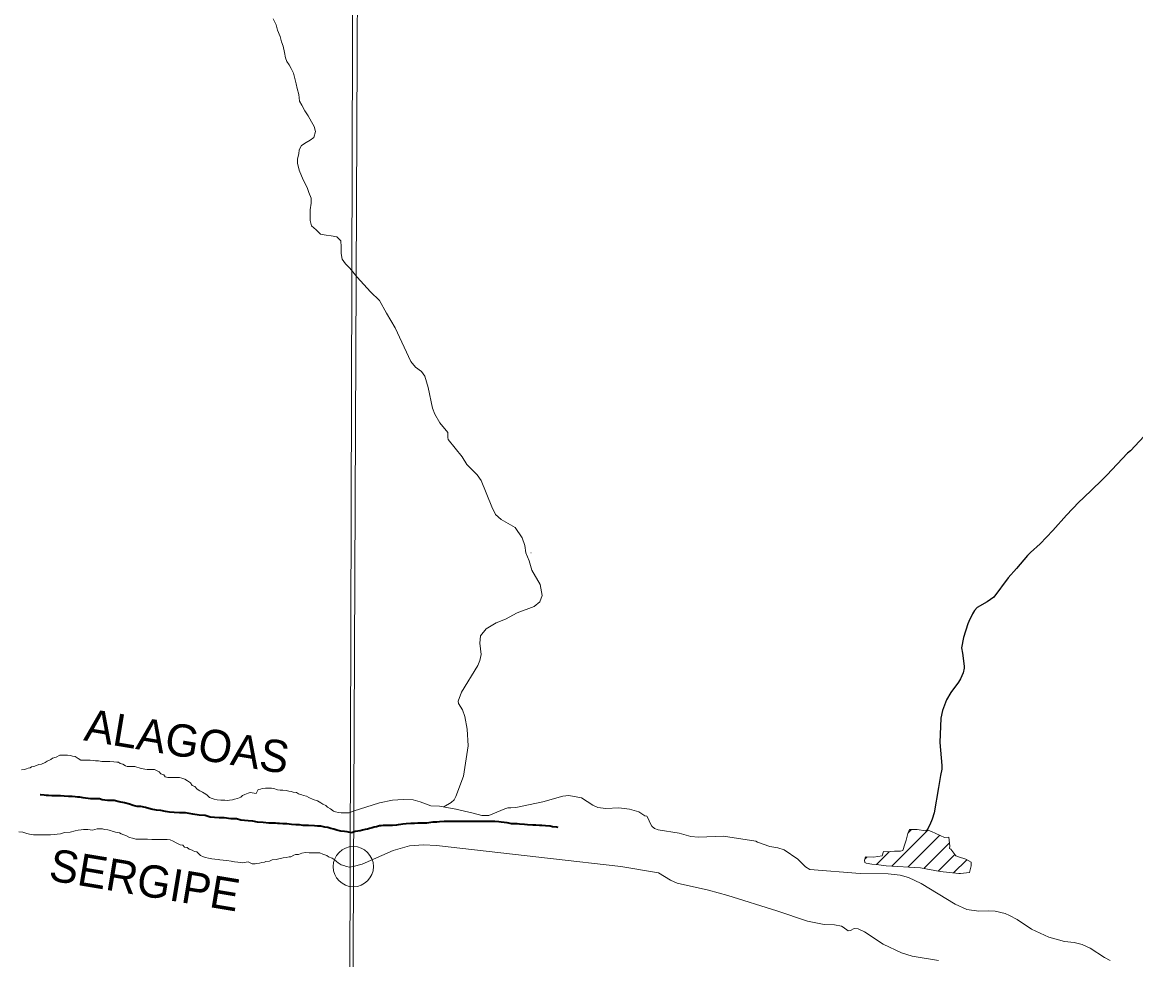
# Model space of a CAD drawing. Extents: x -1643653 to 4543381, y 1624270 to 13878484.
# Drawn here: x 595746 to 598511, y 8904160 to 8906488 of the extents above; entities that cross this region are included whole.
import ezdxf
from ezdxf.enums import TextEntityAlignment as Align

# ---------------------------------------------------------------- set-up
doc = ezdxf.new("R2010")
doc.units = 0
doc.header["$LTSCALE"] = 200
doc.header["$PDMODE"] = 32
doc.header["$PDSIZE"] = 100
doc.linetypes.add('LONG_DASH_SHORT_DASH', pattern=[9.9, 6, -1.2, 1.5, -1.2])
doc.layers.add('6', color=7, linetype='Continuous', lineweight=13)
doc.layers.add('60', color=7, linetype='Continuous', lineweight=13)

msp = doc.modelspace()

# ---------------------------------------------------------------- linework, layer by layer
at = {"layer": '6'}
for p, q in [((597009.3, 8905170.6), (597009.5, 8905170.5)), ((597905.6, 8904392.3), (597995.3, 8904482)), ((597946.4, 8904475.5), (597954.7, 8904483.9)), ((597945.7, 8904390), (598025, 8904469.3)), ((597867.6, 8904396.8), (597899.4, 8904428.5)), ((597984.9, 8904386.8), (598049.1, 8904451)), ((597838.3, 8904409.9), (597844.2, 8904415.7)), ((598021.1, 8904380.5), (598062.5, 8904421.9)), ((598059, 8904376), (598091.6, 8904408.6))]:
    msp.add_line(p, q, dxfattribs=at)
for points in [[(596655.5, 8924715.8), (596593.3, 8909930.3), (596531.7, 8896026.7)], [(596461.2, 8906005.4), (596461.2, 8906022.7), (596463.8, 8906039.2), (596463.4, 8906051.2), (596457.4, 8906065.3), (596453.5, 8906078.3), (596444.6, 8906095.4), (596439.1, 8906106.9), (596433.7, 8906120.9), (596429.8, 8906138.5), (596429.8, 8906149), (596432.9, 8906162), (596433.9, 8906171.5), (596439.5, 8906182), (596451, 8906189.9), (596461, 8906195.4), (596470.1, 8906202.3), (596474.2, 8906216.8), (596471.2, 8906229.4), (596464.2, 8906241.4), (596455.8, 8906256), (596447.9, 8906268), (596439.9, 8906282.6), (596434.5, 8906292.6), (596433, 8906308.7), (596429.1, 8906323.7), (596426.2, 8906335.2), (596422.7, 8906348.8), (596419.3, 8906361.8), (596413.8, 8906373.3), (596408.8, 8906382.4), (596403.4, 8906390.9), (596399.9, 8906400.4), (596397, 8906413.4), (596393.6, 8906429), (596389.6, 8906440), (596386.2, 8906452.6), (596379.7, 8906468.6), (596376.3, 8906481.6), (596368.8, 8906497.2)], [(596838.8, 8905408.9), (596804, 8905452.2), (596802.6, 8905456.8), (596803.3, 8905469.9), (596782.8, 8905493.9), (596770.6, 8905515.5), (596764.7, 8905530.2), (596754.3, 8905581.4), (596745.9, 8905609.6), (596737.4, 8905621.2), (596722.8, 8905631.7), (596710.6, 8905646), (596672.1, 8905729.1), (596650.2, 8905765.8), (596633.6, 8905797.4), (596611.2, 8905818.6), (596577.4, 8905855.5), (596559.7, 8905877.5), (596548.7, 8905888.6), (596540.2, 8905900.2), (596538.3, 8905914.2), (596537.9, 8905930.7), (596537.5, 8905945.2), (596527, 8905955.3), (596513.5, 8905957.9), (596500.5, 8905959.4), (596487, 8905962.5), (596476, 8905972.6), (596464.6, 8905983.1), (596461.1, 8905995.7), (596461.2, 8906005.4)], [(596792.7, 8904540.1), (596811.4, 8904551.1), (596818.4, 8904557.4), (596822.7, 8904565.5), (596841.5, 8904615.9), (596853.2, 8904691.8), (596850.7, 8904732.7), (596845.1, 8904764.5), (596839.3, 8904781), (596829.4, 8904796.5), (596828.9, 8904802.2), (596837.1, 8904824.7), (596877.1, 8904890.7), (596882.8, 8904903.4), (596885.5, 8904918), (596882.5, 8904946.3), (596884.2, 8904964.5), (596897.9, 8904982), (596922.6, 8904996.6), (596946.5, 8905006.2), (596975.3, 8905021.5), (597017.5, 8905037.8), (597031.8, 8905049.4), (597037, 8905065), (597032.3, 8905091.9), (597011.4, 8905127.4), (597004.9, 8905150.7), (596996.7, 8905170.4), (596994.1, 8905188.6), (596987.3, 8905208), (596969.8, 8905234), (596935.4, 8905253.2), (596921.5, 8905266.1), (596912.2, 8905285.1), (596886, 8905350.5), (596875.4, 8905364.7), (596850.4, 8905390), (596838.8, 8905408.9)], [(595744.1, 8904632.1), (595751.7, 8904633.1), (595756.2, 8904634.6), (595760.7, 8904636), (595765.2, 8904637), (595769.2, 8904639), (595774.7, 8904640.4), (595781.2, 8904642.4), (595786.8, 8904645.4), (595793.3, 8904646.3), (595802.8, 8904650.3), (595807.8, 8904653.7), (595816.9, 8904657.2), (595821.4, 8904660.7), (595830.4, 8904663.6), (595839, 8904668.1), (595845, 8904668), (595850, 8904668), (595858, 8904667.9), (595866, 8904667.4), (595870.5, 8904665.8), (595877.5, 8904664.8), (595884.9, 8904659.7), (595891.4, 8904656.2), (595899.4, 8904656.1), (595903.4, 8904656.1), (595910.9, 8904656.1), (595914.9, 8904656), (595922.9, 8904655), (595927.4, 8904654.4), (595934.9, 8904653.9), (595943.4, 8904652.3), (595951.4, 8904652.3), (595956.4, 8904652.3), (595963.4, 8904652.2), (595973.4, 8904651.6), (595980.4, 8904651.1), (595984.9, 8904650.6), (595989.4, 8904647.5), (595995.3, 8904646), (596002.3, 8904641.9), (596006.8, 8904639.9), (596012.8, 8904639.9), (596025.8, 8904639.8), (596041.3, 8904635.2), (596045.8, 8904634.6), (596050.3, 8904633.6), (596056.3, 8904633.1), (596063.8, 8904633), (596067.8, 8904633), (596074.3, 8904632.4), (596079.3, 8904630.4), (596086.2, 8904626.9), (596090.2, 8904622.3), (596097.2, 8904619.3), (596100.7, 8904614.2), (596107.2, 8904613.2), (596113.7, 8904613.2), (596120.7, 8904613.1), (596124.7, 8904613.1), (596128.7, 8904613.1), (596136.2, 8904613), (596142.2, 8904611), (596149.6, 8904608.4), (596156.1, 8904604.4), (596163.6, 8904599.3), (596168, 8904593.3), (596174.5, 8904590.2), (596180.5, 8904583.7), (596186.9, 8904580.1), (596193.4, 8904576.1), (596197.9, 8904574.1), (596204.4, 8904570), (596211.3, 8904563.4), (596217.3, 8904560.4), (596222.8, 8904558.9), (596229.8, 8904557.3), (596238.8, 8904556.3), (596245.3, 8904556.2), (596249.3, 8904556.2), (596255.8, 8904556.1), (596260.3, 8904556.6), (596268.3, 8904557.6), (596272.8, 8904559), (596280.8, 8904561), (596288.9, 8904564.4), (596292.9, 8904567.9), (596298.4, 8904570.9), (596307, 8904574.3), (596312, 8904575.3), (596327, 8904573.2), (596331.5, 8904582.7), (596337.5, 8904584.1)], [(596337.5, 8904584.1), (596341.6, 8904585.6), (596350.1, 8904586.6), (596357.6, 8904586.5), (596364.6, 8904586), (596371.1, 8904585.9), (596379.5, 8904581.9), (596386.5, 8904581.3), (596393.5, 8904581.3), (596401.5, 8904580.7), (596408, 8904579.2), (596414, 8904578.1), (596419, 8904576.6), (596427, 8904575.5), (596432, 8904572.5), (596440, 8904569.4), (596444.5, 8904567.9), (596452, 8904566.9), (596457.4, 8904563.3), (596468.4, 8904558.2), (596478.9, 8904554.7), (596487.3, 8904550.1), (596492.3, 8904546.6), (596500.3, 8904543), (596504.3, 8904539), (596511.7, 8904535.4), (596519.2, 8904529.4), (596523.7, 8904527.8), (596531.7, 8904525.8), (596538.2, 8904524.7), (596545.2, 8904524.7), (596549.2, 8904524.7), (596554.2, 8904525.1), (596558.2, 8904525.1), (596568.1, 8904529.4), (596633, 8904549.7), (596665.5, 8904556.5), (596692.3, 8904558.4), (596717.2, 8904557), (596733.8, 8904552.4)], [(596822.7, 8904565.5), (596818.4, 8904557.4), (596811.4, 8904551.1), (596792.7, 8904540.1)], [(596823.3, 8904534.6), (596822.9, 8904534.3), (596866.1, 8904524.6), (596887.5, 8904518.1), (596904.4, 8904518.5), (596944.7, 8904535.2), (596952.2, 8904537.4), (596959.2, 8904537.7), (596972.2, 8904538.7), (597038.5, 8904552.3), (597088.9, 8904566.9), (597103.5, 8904567.8), (597135.1, 8904562.2), (597163.3, 8904544.4), (597175.5, 8904538.6), (597195.2, 8904535.8), (597227.3, 8904537.4), (597253.9, 8904534.1), (597277.1, 8904527.3), (597291.9, 8904517.4), (597296.9, 8904516.7), (597300.6, 8904511.3), (597305.1, 8904499.1), (597310, 8904491.8), (597315.9, 8904486.6), (597325.4, 8904483.2), (597377.2, 8904474.8), (597406.8, 8904466.6), (597425.4, 8904464.6), (597488, 8904467), (597567.9, 8904454.9)], [(596733.8, 8904552.4), (596760.4, 8904542.1), (596781.9, 8904541.7), (596822.9, 8904534.3)], [(596113, 8904457.9), (596106, 8904458.5), (596097.5, 8904459.1), (596092.5, 8904459.1), (596084.5, 8904459.1), (596079.5, 8904459.2), (596067.5, 8904459.2), (596057, 8904459.3), (596050, 8904459.4), (596042, 8904459.4), (596036.5, 8904459.5), (596028, 8904459.5), (596020, 8904462.6), (596012, 8904463.6), (596005, 8904467.7), (595998.5, 8904470.7), (595991.5, 8904472.8), (595987.1, 8904475.8), (595977.6, 8904476.9), (595969.6, 8904479.9), (595965.1, 8904481.5), (595958.6, 8904482.5), (595950.1, 8904484.1), (595945.1, 8904485.1), (595936.6, 8904485.2), (595932.1, 8904485.2), (595920.1, 8904482.3), (595908.6, 8904483.3), (595897.6, 8904483.4), (595892.1, 8904482.9), (595885.1, 8904482), (595877, 8904480.5), (595865, 8904477.1), (595851, 8904476.2), (595840.5, 8904473.3), (595832.5, 8904471.8), (595827, 8904470.9), (595816.4, 8904470.4), (595808.4, 8904470.5), (595798.4, 8904470.5), (595789.4, 8904470.6), (595783.9, 8904470.6), (595773.9, 8904470.7), (595763.9, 8904472.3), (595756.9, 8904473.8), (595747, 8904477.4), (595737, 8904478)], [(596137.9, 8904445.3), (596128.4, 8904450.8), (596120.5, 8904454.9), (596113, 8904457.9)], [(597567.9, 8904454.9), (597572.2, 8904452.6), (597602.6, 8904441.6), (597622.9, 8904438.2), (597638, 8904432.9), (597672.2, 8904410.2), (597691.4, 8904390.6), (597701.7, 8904384.3), (597826.9, 8904374.3), (597896.6, 8904373.8), (597926.2, 8904370), (597946.7, 8904364.9), (597978.4, 8904349.8), (598062.8, 8904298.6), (598092.1, 8904285.4), (598121.7, 8904280.6), (598145.7, 8904281.8), (598162.6, 8904280.9), (598187.1, 8904274.8), (598198.3, 8904270.4), (598217.2, 8904259.9), (598252.8, 8904236.5), (598295.7, 8904216.1), (598334.6, 8904205.9), (598358.9, 8904203.3), (598378.5, 8904198.1), (598398.6, 8904189.3), (598434, 8904165.6), (598448.2, 8904158.3)], [(596412.8, 8904415.9), (596408.8, 8904415.9), (596401.3, 8904414.5), (596394.3, 8904413), (596387.2, 8904411.6), (596383.2, 8904410.6), (596376.2, 8904409.6), (596366.7, 8904408.2), (596360.2, 8904405.2), (596351.2, 8904404.3), (596347.2, 8904402.8), (596341.2, 8904401.9), (596335.1, 8904399.9), (596328.6, 8904398.9), (596324.1, 8904398.5), (596317.1, 8904398.5), (596307.2, 8904403.6), (596293.1, 8904401.2), (596281.1, 8904402.3), (596273.1, 8904403.8), (596264.6, 8904405.4), (596253.7, 8904406.4), (596244.7, 8904407.5), (596236.7, 8904408.1), (596232.2, 8904409.1), (596224.2, 8904410.2), (596216.7, 8904411.2), (596208.7, 8904412.8), (596201.2, 8904414.3), (596196.2, 8904415.8), (596188.7, 8904418.9), (596184.2, 8904422.9), (596179.3, 8904428), (596173.3, 8904429), (596167.8, 8904432.1), (596160.3, 8904435.1), (596155.8, 8904438.6), (596148.8, 8904439.7), (596144.9, 8904444.7), (596137.9, 8904445.3)], [(597784.5, 8904240.9), (597780.8, 8904243.5), (597763, 8904246.9), (597737.7, 8904248), (597696.4, 8904255.7), (597619.9, 8904282.1), (597498.2, 8904319.6), (597450, 8904332.9), (597372.6, 8904350.3), (597356, 8904357.7), (597326.5, 8904376.3), (597232.9, 8904391.8), (597058.1, 8904411.6), (596775.1, 8904444.1), (596742.4, 8904446), (596707.5, 8904442.8), (596667.4, 8904431.6), (596590.1, 8904397.6), (596568.1, 8904391.5), (596558.7, 8904389.9), (596551.2, 8904391.5), (596544.2, 8904394), (596537.7, 8904395.6), (596530.7, 8904401.1), (596526.2, 8904404.6), (596520.3, 8904409.2), (596515.8, 8904412.2), (596506.8, 8904415.8), (596502.3, 8904419.3), (596492.4, 8904422.4), (596485.4, 8904425.4), (596475.9, 8904426), (596467.4, 8904426.1), (596458.4, 8904426.1), (596449.4, 8904426.2), (596440.4, 8904425.2), (596431.8, 8904421.3), (596424.8, 8904421.3), (596420.3, 8904419.9), (596412.8, 8904415.9)], [(598021.9, 8904158.5), (597956.3, 8904169.2), (597929.3, 8904177.5), (597883.8, 8904198.6), (597837.6, 8904229.6), (597822.4, 8904236.9), (597812.2, 8904237.9), (597802.9, 8904232.5), (597797.6, 8904231.9), (597784.5, 8904240.9)]]:
    msp.add_lwpolyline(points, dxfattribs=at)
for points in [[(596575.8, 8909932.4), (585614.8, 8909969.8), (585583.8, 8898914.4), (596544.8, 8898874.9)], [(598076.1, 8904374.3), (598098.6, 8904377.3), (598102.8, 8904393.2), (598103.1, 8904402.4), (598089.5, 8904409.8), (598071, 8904415.8), (598065, 8904418.6), (598052.1, 8904435.2), (598049.2, 8904436.8), (598050, 8904442.7), (598047.6, 8904465), (598036.8, 8904463.8), (598004.4, 8904478.8), (597993.7, 8904482.5), (597989.2, 8904480.8), (597968.7, 8904483.6), (597949.6, 8904484), (597945.8, 8904474), (597941.6, 8904457.1), (597937.6, 8904447), (597933.3, 8904431.5), (597927.5, 8904429.7), (597912, 8904430), (597894.4, 8904427.9), (597885.2, 8904428.9), (597883.8, 8904426.4), (597882.9, 8904420.8), (597881.3, 8904418.1), (597859.9, 8904414.8), (597840.3, 8904416), (597837.6, 8904407.7), (597838.4, 8904401.7), (597841.9, 8904400), (597856, 8904397.5), (597873.8, 8904396.3), (597891.4, 8904393.1), (597976.5, 8904388.3), (598025.4, 8904379.8), (598072.1, 8904374.5)]]:
    msp.add_lwpolyline(points, close=True, dxfattribs=at)
at = {"layer": '6', "lineweight": 25}
for points in [[(598811.5, 8905757.4), (598733.5, 8905676.3), (598498.6, 8905424.2), (598490.9, 8905418), (598439.8, 8905363.3), (598425.4, 8905349.3)], [(598425.4, 8905349.3), (598382.1, 8905307.4), (598370, 8905296.7), (598339.1, 8905264), (598305.9, 8905226), (598273.9, 8905193.3), (598249.7, 8905171.9), (598243, 8905164.1)], [(598243, 8905164.1), (598215.7, 8905131.8), (598194.5, 8905108.4), (598159.2, 8905060.4), (598142.4, 8905049.3), (598117.3, 8905035), (598111.1, 8905027.6), (598105.9, 8905019.5), (598097.1, 8905000.6)], [(598097.1, 8905000.6), (598094.2, 8904994.3), (598084, 8904960.9), (598079.1, 8904934.7), (598081, 8904921.7)], [(598081, 8904921.7), (598085.6, 8904889.7), (598085.6, 8904884.2), (598082.7, 8904873.1), (598076, 8904857.5), (598071.3, 8904849.5), (598052.2, 8904824.1), (598041.5, 8904805.9), (598031.7, 8904779.5), (598027.3, 8904760), (598024.5, 8904700), (598029.9, 8904642.3), (598029.5, 8904633.9), (598026.3, 8904618.1), (598021.2, 8904587.6)], [(598021.2, 8904587.6), (598010.6, 8904524.8), (598006.1, 8904509.6), (598000.4, 8904495.6), (597993.4, 8904482.7)]]:
    msp.add_lwpolyline(points, dxfattribs=at)
at = {"layer": '6', "linetype": 'LONG_DASH_SHORT_DASH', "lineweight": 35}
for points in [[(596403.1, 8904497.6), (596393.1, 8904498.1), (596385.2, 8904498.7), (596380.2, 8904498.7), (596375.2, 8904499.2), (596367.2, 8904499.3), (596358.7, 8904499.8), (596344.2, 8904500.9), (596330.2, 8904502), (596318.2, 8904504.5), (596307.2, 8904505.1), (596298.2, 8904506.1), (596288.7, 8904507.2), (596278.2, 8904509.8), (596264.2, 8904510.3), (596247.2, 8904512.9), (596234.7, 8904513), (596223.2, 8904513.5), (596212.2, 8904514.6), (596200.3, 8904518.2), (596185.3, 8904519.2), (596169.8, 8904521.8), (596151.3, 8904524.9), (596136.3, 8904525), (596122.8, 8904526.1), (596111.8, 8904527.1), (596101.3, 8904528.2), (596090.4, 8904531.3), (596079.4, 8904531.8), (596065.9, 8904534.4), (596051.9, 8904538), (596040.4, 8904540.5), (596030.9, 8904541.1), (596021.4, 8904543.6), (596012, 8904546.7), (596000, 8904549.8), (595987, 8904552.8), (595974.5, 8904555.4), (595957.5, 8904556), (595944.5, 8904557.1), (595937.6, 8904559.6), (595929.5, 8904559.6), (595924, 8904559.7), (595915.6, 8904560.2), (595909.6, 8904560.7), (595903.1, 8904561.8), (595897.1, 8904562.3), (595889.1, 8904563.9), (595883.1, 8904564.4), (595877.1, 8904564.9), (595870.1, 8904566), (595860.6, 8904566), (595850.1, 8904566.6), (595840.6, 8904567.1), (595830.1, 8904567.2), (595819.1, 8904567.2), (595811.1, 8904567.8), (595805.6, 8904567.8), (595800.1, 8904568.8), (595791.6, 8904569.4), (595790.2, 8904569.7)], [(596573, 8904478.7), (596564, 8904475.2), (596553, 8904478.3), (596546, 8904478.8), (596537, 8904479.3), (596527, 8904481.9), (596519.6, 8904484.9), (596512.1, 8904486), (596504.6, 8904488.5), (596497.1, 8904489.6), (596487.6, 8904492.1), (596479.1, 8904492.2), (596471.6, 8904492.7), (596456.6, 8904493.3), (596443.6, 8904493.9), (596434.1, 8904494.9), (596425.1, 8904495.5), (596414.6, 8904496.5), (596403.1, 8904497.6)], [(597057.4, 8904492), (597045.7, 8904492.5), (597036, 8904494), (597030.4, 8904494), (597021.8, 8904494.5), (597014.2, 8904494.5), (597000.4, 8904495.6), (596993.3, 8904496.1), (596981.1, 8904496.6), (596975, 8904497.6), (596965.8, 8904498.1), (596961.2, 8904498.1), (596954.1, 8904499.7), (596950, 8904500.2), (596942.9, 8904500.7), (596935.3, 8904501.7), (596929.7, 8904502.7), (596920, 8904503.7), (596907.3, 8904503.7), (596895.6, 8904503.7), (596890, 8904503.7), (596880.3, 8904503.7), (596874.2, 8904503.7), (596857.9, 8904503.7), (596850.8, 8904503.7), (596839.1, 8904503.7), (596833, 8904503.7), (596821.8, 8904503.7), (596815.7, 8904503.7), (596801.4, 8904503.7), (596793.8, 8904503.7), (596782.1, 8904502.7), (596776, 8904502.2), (596765.8, 8904501.7), (596760.7, 8904500.7), (596750.6, 8904499.6), (596741.9, 8904499.6), (596737.3, 8904499.6), (596728.7, 8904499.6), (596720.5, 8904498.6), (596710.8, 8904498.6), (596699.7, 8904498.1), (596691, 8904496.6), (596686.4, 8904496.1), (596679.3, 8904495.6), (596675.2, 8904494.5), (596665.6, 8904494), (596659.5, 8904494), (596654.4, 8904494), (596648.8, 8904494), (596642.7, 8904494), (596637.1, 8904492.5), (596633, 8904492.5), (596625.9, 8904490.4), (596620.3, 8904489.4), (596614.7, 8904487.9), (596608.6, 8904486.3), (596603.5, 8904484.8), (596597.4, 8904483.8), (596591.3, 8904482.3), (596585.2, 8904480.7), (596579.1, 8904479.7), (596573, 8904478.7), (596573, 8904478.7), (596573, 8904478.7)], [(597076.6, 8904488.8), (597073.7, 8904489.4), (597063, 8904490.4), (597057.4, 8904492)]]:
    msp.add_lwpolyline(points, dxfattribs=at)
at = {"layer": '6'}
msp.add_point((596568.1, 8904391.5), dxfattribs=at)
at = {"layer": '60', "lineweight": 25}
msp.add_spline([(814781, 9009175.5), (814787.2, 9009173.4), (814796.9, 9009173.4), (814799.4, 9009172.4), (814805.1, 9009174.5), (814805.6, 9009176.5), (814811.7, 9009179.5), (814811.7, 9009179.5), (814801.5, 9009181), (814790.7, 9009181.5), (814784.1, 9009183.1), (814777.4, 9009185.1), (814778.4, 9009175.5)], degree=3, dxfattribs=at)

# ---------------------------------------------------------------- texts
at = {"layer": '6'}
for s, p in [('ALAGOAS', (596148.9, 8904663.4)), ('SERGIPE', (596043.6, 8904319))]:
    msp.add_text(s, height=80, rotation=350.533, dxfattribs=at).set_placement(p, align=Align.CENTER)

doc.saveas('drawing.dxf')
